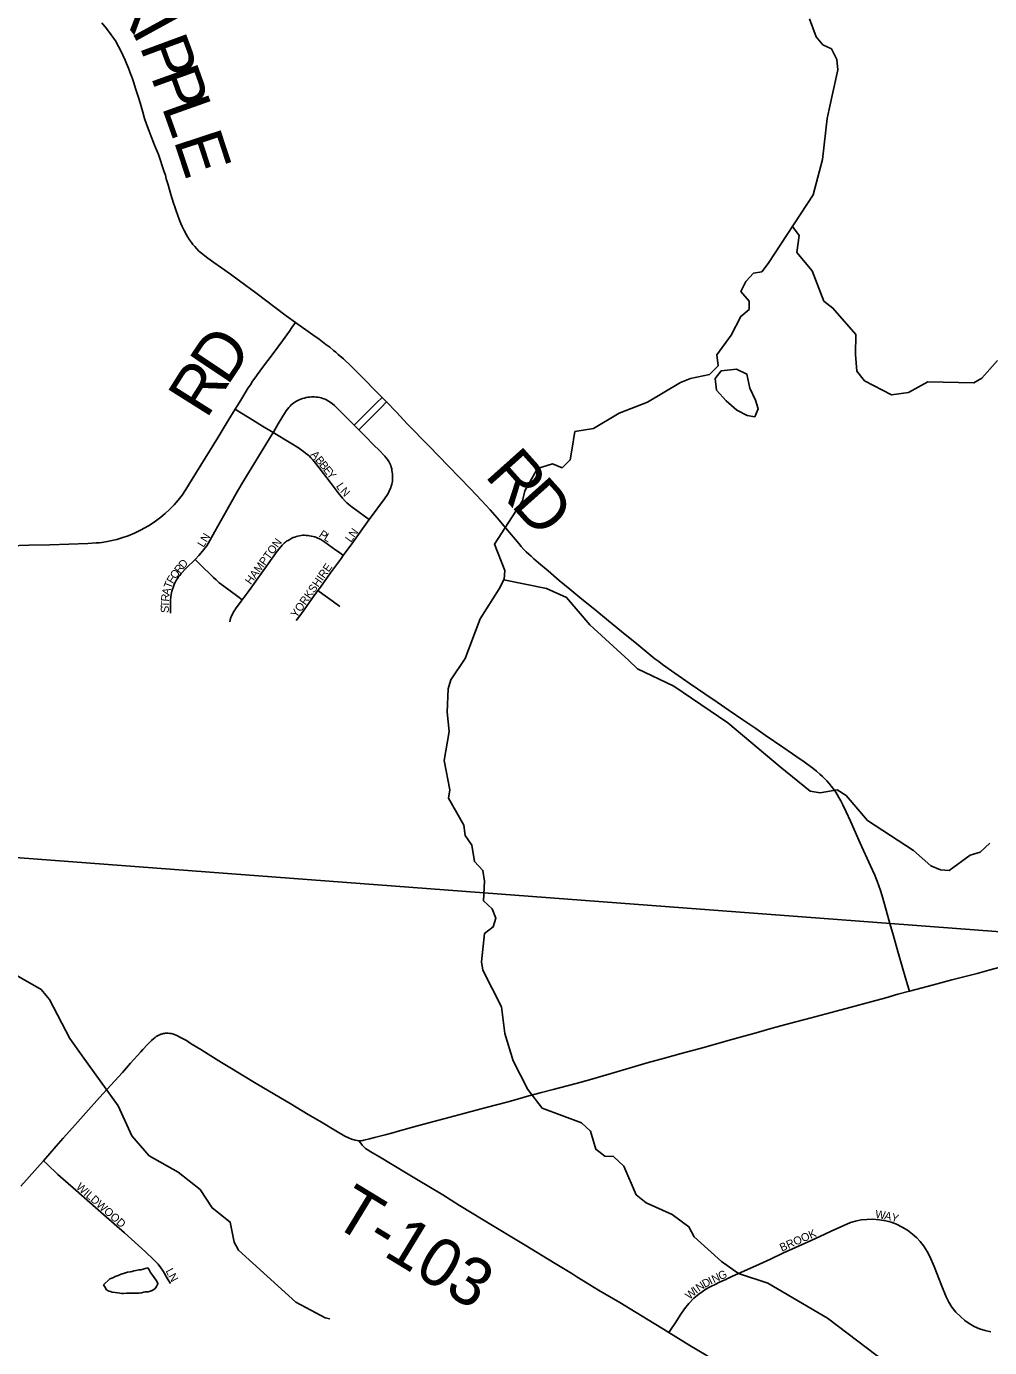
# Model space of a CAD drawing. Extents: x 1410790 to 1770854, y 448063 to 770588.
# Drawn here: x 1538714 to 1544730, y 611215 to 619468 of the extents above; entities that cross this region are included whole.
import ezdxf

# ---------------------------------------------------------------- set-up
doc = ezdxf.new("R2010")
doc.units = 0
for name, color, linetype in [('GM_X_County_Road', 7, 'Continuous'), ('GM_X_County_Road_Text', 7, 'Continuous'), ('GM_X_Minor_Lake', 7, 'Continuous'), ('GM_X_Minor_River', 7, 'Continuous'), ('GM_X_Township', 7, 'Continuous'), ('GM_X_Township_Road', 7, 'Continuous'), ('GM_X_Township_Road_Text', 7, 'Continuous'), ('GM_X_Township_Subdivision', 7, 'Continuous'), ('GM_X_Township_Subdivision_Text', 7, 'Continuous')]:
    doc.layers.add(name, color=color, linetype=linetype)

msp = doc.modelspace()

# ---------------------------------------------------------------- linework, layer by layer
at = {"layer": 'GM_X_County_Road'}
for points in [[(1539185.9, 619491.1), (1539215.3, 619455.5), (1539244.5, 619415.7), (1539270, 619377.2), (1539290.1, 619343.2), (1539302.3, 619319.8), (1539317.4, 619288.8), (1539331.3, 619257.9), (1539340.4, 619235.8), (1539351.7, 619207.6), (1539363, 619177.6), (1539373.8, 619146.8), (1539384.7, 619114.7), (1539395.5, 619080.4), (1539405.9, 619048.3), (1539418.1, 619011), (1539428.9, 618975.4), (1539441.1, 618932.4), (1539452.7, 618893.2), (1539464.5, 618857.3), (1539480.6, 618812.6), (1539492.7, 618780.5), (1539507.5, 618742.8), (1539514.9, 618725.2)], [(1539514.9, 618725.2), (1539527, 618696.3), (1539538.3, 618668.1), (1539550, 618635.5), (1539564.8, 618591.7), (1539575.6, 618558.7), (1539582.1, 618537.9), (1539588.2, 618515.8), (1539599.1, 618478.4), (1539616.9, 618417.2), (1539633.3, 618364.3), (1539640.7, 618341.7), (1539649.8, 618314.8), (1539659.4, 618287.4), (1539670.7, 618256.6), (1539678.1, 618237.5), (1539686.3, 618218.9), (1539698.9, 618193.3), (1539713.2, 618166.3), (1539722.8, 618150.7), (1539733.2, 618135.5), (1539744.7, 618118.1), (1539753.6, 618106.5), (1539765.3, 618092.6), (1539777.4, 618079.6), (1539792.2, 618064.8), (1539807, 618052.2), (1539828.2, 618034.9), (1539847.8, 618020.5), (1539884.6, 617993.6), (1539933.3, 617959.3), (1539988.4, 617920.3), (1540044.3, 617879.3), (1540146.6, 617802.8), (1540337.3, 617659), (1540394.2, 617618.5)], [(1540394.2, 617618.5), (1540502.7, 617541.4), (1540542.2, 617513.2), (1540585.2, 617481.5), (1540609, 617463.2), (1540632, 617444.2), (1540647.2, 617432), (1540662.5, 617419.1), (1540694.3, 617390.5), (1540739.8, 617347.6), (1540823.7, 617264.4), (1540895.5, 617192.3), (1540935.8, 617150.5)], [(1540935.8, 617150.5), (1540963.5, 617121.9)], [(1540963.5, 617121.9), (1541023, 617059.9), (1541095.4, 616984.1), (1541227.6, 616847.4), (1541351.3, 616720.9), (1541488.3, 616579.9), (1541557.9, 616505.7), (1541610.9, 616447.5), (1541654.4, 616398.2), (1541709.3, 616332.8), (1541789.1, 616237.2), (1541805.2, 616218.9), (1541822, 616200.9), (1541836, 616186.3), (1541852, 616171), (1541866.4, 616157.7), (1541883.7, 616142.7), (1541912.4, 616117.8), (1541973.3, 616066.1), (1542042.6, 616007.5), (1542107.7, 615953.3), (1542184.1, 615890.8), (1542265.7, 615825.2), (1542350.4, 615754.5), (1542454.1, 615669), (1542514, 615621.2), (1542565.2, 615578.7), (1542640.3, 615517.5), (1542663.7, 615499.7), (1542688, 615481.9), (1542743.6, 615442.4), (1542853, 615365.9), (1542951.5, 615298.3), (1543027.9, 615245.8), (1543103.4, 615195), (1543189.8, 615136.4), (1543269.6, 615081.9), (1543329.1, 615040.7), (1543440, 614964.5), (1543499.5, 614923.8), (1543540.4, 614894.7), (1543563, 614879.1), (1543588.2, 614861.2), (1543626.4, 614833.5), (1543649, 614814.8), (1543669.4, 614797.5), (1543686.7, 614781.4), (1543701.9, 614766.6), (1543713.2, 614755.3), (1543729.3, 614738.4), (1543741.9, 614722.4), (1543752.7, 614708), (1543769.2, 614684.6), (1543778.3, 614670.3), (1543788.7, 614651.6), (1543800.9, 614629.9), (1543813.4, 614606.1), (1543834.4, 614562), (1543861.2, 614502.7), (1543885.3, 614450), (1543922.8, 614366.5), (1543987.5, 614223.7), (1544013.8, 614165.6), (1544020.9, 614148.1), (1544028.2, 614128.9), (1544048.8, 614069.9), (1544063.5, 614022.8), (1544091.6, 613925), (1544112.6, 613849.1), (1544125.9, 613801.5)], [(1544125.9, 613801.5), (1544158.1, 613688.2), (1544188.3, 613580.9), (1544217.5, 613481.5), (1544229.4, 613441.1)], [(1544229.4, 613441.1), (1544269, 613452), (1544380, 613481.1), (1544494.3, 613510.9), (1544653, 613552.3), (1544725.9, 613571.9), (1544836.7, 613601.9), (1544960.2, 613635.3), (1545037.6, 613655.9)], [(1540791.6, 612506.6), (1540798.9, 612506.4), (1540804.2, 612506.7), (1540814.8, 612508.1), (1540822.1, 612509.5), (1540856.4, 612518.4), (1540888.3, 612526.5), (1540954.5, 612544.5), (1541002.1, 612557.1), (1541030.5, 612564.8), (1541157.2, 612599.4), (1541321.8, 612644), (1541445.6, 612676.2), (1541493, 612689), (1541594.4, 612715.5), (1541714.5, 612748.1), (1541780.7, 612766.8), (1541853.3, 612787), (1541932.5, 612808.2), (1542005.4, 612827.4), (1542091, 612849.8), (1542148, 612864.8), (1542231.8, 612887.9), (1542366.8, 612926.8), (1542458.1, 612953.5), (1542590.7, 612992.8), (1542699.5, 613022.9), (1542804, 613051), (1542946.4, 613090), (1543098.2, 613132.2), (1543180.4, 613154.9), (1543271.9, 613180.7), (1543373.1, 613208.9), (1543480.5, 613238.6), (1543617, 613274.1), (1543772.1, 613316.6), (1544082.5, 613400.3), (1544158.3, 613421.5), (1544229.4, 613441.1)], [(1538820.1, 612382), (1538900.3, 612473.4), (1538943.5, 612522.5), (1539002.7, 612588.2), (1539086.2, 612680.6), (1539171.6, 612775.8), (1539266.3, 612880.4), (1539314.6, 612934), (1539364.6, 612990.5), (1539428.1, 613061.4), (1539441.3, 613076.2), (1539469.8, 613107.6), (1539480.4, 613118.6), (1539495.4, 613132.9), (1539511.3, 613147), (1539518, 613152.3), (1539525.1, 613157.2), (1539540.4, 613166), (1539546.9, 613169.2), (1539550.6, 613170.7), (1539554.1, 613172), (1539558.3, 613173.3), (1539564.4, 613175), (1539569.3, 613176.3), (1539576.4, 613177.6), (1539582.2, 613178.5), (1539586.8, 613178.9), (1539594.3, 613179.2), (1539599.8, 613178.9), (1539610.7, 613177.6), (1539618.8, 613176), (1539632.5, 613172.5), (1539639.4, 613170.2), (1539653.5, 613164.6), (1539681.4, 613150.5), (1539713.8, 613131.9), (1539744.3, 613112.8), (1539802.7, 613076.7), (1539850.1, 613047.3), (1539933.8, 612995.8), (1539995, 612957.7), (1540070.6, 612911.7), (1540149.8, 612865.1), (1540265.2, 612796.1), (1540360.9, 612738.7), (1540473.4, 612671.1), (1540547.5, 612628.9), (1540656.8, 612562.6), (1540702.4, 612536), (1540726.2, 612524), (1540744.2, 612516.6), (1540753, 612513.6), (1540767.4, 612509.5), (1540780.9, 612507.3), (1540788.6, 612506.7), (1540791.6, 612506.6)], [(1538679.1, 612222.4), (1538818.1, 612379.7), (1538820.1, 612382)]]:
    msp.add_lwpolyline(points, dxfattribs=at)
at = {"layer": 'GM_X_Minor_Lake'}
for points in [[(1543264.1, 617028.2), (1543285, 617077.9), (1543268.1, 617132.5), (1543233.4, 617207.5), (1543215.1, 617296.3), (1543149.6, 617325.8), (1543053.2, 617315.9), (1543016.3, 617268.5), (1543024.9, 617196)], [(1543024.9, 617196), (1543085, 617127.9), (1543151.7, 617070.9), (1543216.8, 617037.2), (1543264.1, 617028.2)], [(1539195.4, 611606.3), (1539236.3, 611643.4), (1539254.5, 611651), (1539268.7, 611658.7), (1539286.9, 611664.3), (1539307.1, 611673.8), (1539327.3, 611679.4), (1539345.4, 611684.9), (1539363.5, 611688.5), (1539375.6, 611690.2), (1539385.7, 611694), (1539397.8, 611695.7), (1539415.9, 611699.3), (1539429.9, 611701), (1539444.1, 611704.7), (1539456.2, 611708.4), (1539472.3, 611712), (1539482, 611699.7), (1539489.7, 611683.5), (1539501.3, 611667.2), (1539513, 611652.8), (1539522.7, 611638.5), (1539530.4, 611624.3), (1539536.1, 611612.2), (1539527.8, 611596.3), (1539517.5, 611584.5), (1539503.2, 611572.8), (1539489, 611567.2), (1539474.9, 611563.5), (1539456.9, 611561.9), (1539446.8, 611560.1), (1539432.7, 611556.5), (1539418.6, 611554.8), (1539404.6, 611555.1), (1539380.5, 611553.7), (1539368.5, 611554), (1539354.5, 611554.3), (1539338.5, 611554.7), (1539320.4, 611553.2), (1539310.4, 611553.4), (1539298.4, 611553.7), (1539284.4, 611556), (1539268.5, 611558.4), (1539250.5, 611560.8), (1539238.5, 611565.2), (1539228.6, 611567.4), (1539214.7, 611575.8), (1539203.1, 611594.1), (1539195.4, 611606.3)]]:
    msp.add_lwpolyline(points, dxfattribs=at)
at = {"layer": 'GM_X_Minor_River'}
for points in [[(1543606.1, 619514.3), (1543648, 619403), (1543689.1, 619351.9), (1543742.7, 619328.7), (1543775.5, 619261.7), (1543782.3, 619197.3), (1543729.5, 618951.5), (1543716.3, 618891.6), (1543687.4, 618637.2), (1543629.1, 618415.6), (1543348.5, 617986), (1543307.4, 617934.7), (1543255.2, 617925.8), (1543208.1, 617874.7), (1543176.9, 617811.1), (1543227.8, 617751.8), (1543228.8, 617699.5), (1543175.9, 617656.5), (1543115.6, 617539.4), (1543027.1, 617416.8), (1543035.8, 617348.4), (1542980.7, 617293.4), (1542862.1, 617267.8), (1542799.5, 617243.1), (1542592.9, 617121.1), (1542417.3, 617052.7), (1542257.2, 616955.8), (1542140.7, 616936.3), (1542120.4, 616820.3), (1542111.3, 616760.2), (1542060.3, 616711.2), (1542000.6, 616734.6), (1541905.9, 616706.5), (1541827.1, 616565.7), (1541813.9, 616503.8), (1541638.5, 616232.6), (1541703.5, 616068.5), (1541698.4, 616014.4), (1541667.2, 615954.9), (1541549.5, 615766.8), (1541454.6, 615520), (1541365.9, 615385.4), (1541348.8, 615329.6), (1541342, 615183.2), (1541355.7, 615062.5), (1541324.3, 614882.6), (1541358.8, 614699.2), (1541349.8, 614647.2), (1541446.7, 614478.5), (1541455.5, 614414.1), (1541496.4, 614353), (1541512.4, 614250.3), (1541565.5, 614194.9), (1541576.2, 614128.5), (1541569.9, 614006.2), (1541623, 613954.9), (1541645.9, 613896.2), (1541628.8, 613842.4), (1541576, 613801.4), (1541556.6, 613625.2), (1541565.6, 613572.9), (1541681.4, 613343.6), (1541702.2, 613176.6), (1541755, 613004.9), (1541845.8, 612826.4), (1541935.7, 612710.1), (1542182.3, 612618.4), (1542237.4, 612567), (1542271.3, 612454), (1542326.5, 612410.6), (1542380.5, 612407.4), (1542445.5, 612347.8), (1542522.2, 612169.6), (1542585.3, 612118.1), (1542748.2, 612046.3), (1542852.9, 611969.8), (1542885.7, 611906.9), (1543055, 611752.8)], [(1543499.3, 618217), (1543540.1, 618162.6), (1543526, 618054.5), (1543622, 617941.9), (1543694.5, 617751.6), (1543751.8, 617708.2), (1543894.8, 617542.5), (1543892.4, 617418), (1543900.4, 617313.5), (1543949.4, 617254.2), (1544117.9, 617166.2), (1544224.4, 617181.9), (1544345.8, 617247.5), (1544632.1, 617241.3), (1544682.7, 617270.3), (1544781, 617380.6)], [(1541696.3, 616010.4), (1541963.7, 615956.5), (1542088.8, 615899.5), (1542233.7, 615729.8), (1542477.9, 615507.7), (1542530.9, 615454.3), (1542757.2, 615347), (1543095.3, 615116.8), (1543422.5, 614842.7), (1543609.9, 614690.1), (1543671.8, 614680.7), (1543778.3, 614698.5), (1543835.7, 614663.1), (1543966.9, 614507.7), (1544255.7, 614318.8), (1544308.9, 614271.5), (1544364.1, 614224.1), (1544423.7, 614198.8), (1544477.7, 614195.6), (1544609.7, 614291), (1544672.1, 614309.7), (1544731.3, 614364.6)], [(1538488.3, 613632.2), (1538807.3, 613450.6), (1538858.2, 613389.3), (1538985.7, 613145.8), (1539061.8, 613037.8), (1539288.1, 612723.8), (1539372.7, 612537.4), (1539480.5, 612412.7), (1539662.8, 612310.4), (1539798.9, 612203.1), (1539874.8, 612087), (1539987.3, 611998.3), (1540010.9, 611873.4), (1540038, 611822.7), (1540396.3, 611497.9), (1540521.2, 611431), (1540580.7, 611399.6), (1540608.7, 611395)], [(1543055, 611752.8), (1543161.7, 611678.2), (1543344.8, 611616.1), (1543717.2, 611397.3), (1544029.2, 611163.8), (1544221.3, 611051.3), (1544472, 610963.6), (1544667.5, 610817), (1544718.3, 610751.7), (1545088.1, 610294.3), (1545212.5, 610201.4), (1545320, 610166.9), (1545434.1, 610160.4), (1545437.9, 610152.3)]]:
    msp.add_lwpolyline(points, dxfattribs=at)
at = {"layer": 'GM_X_Township'}
for points in [[(1545541.7, 613754.8), (1544111, 613862.9), (1536959.1, 614403.3), (1531259.4, 614833.9)], [(1531259.4, 614833.9), (1536959.1, 614403.3), (1544111, 613862.9), (1545541.7, 613754.8)]]:
    msp.add_lwpolyline(points, dxfattribs=at)
at = {"layer": 'GM_X_Township_Road'}
for points in [[(1540189.7, 617336.4), (1540255.7, 617424.4), (1540314.3, 617504.2), (1540356.9, 617565), (1540372.9, 617588), (1540394.2, 617618.5)], [(1540018, 617075.9), (1540053.3, 617134), (1540099.8, 617209.4), (1540113, 617229.5), (1540126.8, 617250.8), (1540147.7, 617279.4), (1540155.9, 617290.6)], [(1540155.9, 617290.6), (1540189.7, 617336.4)], [(1538610.4, 616223.7), (1538728.5, 616227.1), (1538859.6, 616230.3), (1539098.9, 616237.7), (1539149, 616240.8), (1539168.1, 616242.5), (1539186.3, 616244.7), (1539220.1, 616249.9), (1539247.9, 616255.5), (1539279.3, 616263.4), (1539310.6, 616272.2), (1539350.5, 616286.2), (1539389.7, 616302.4), (1539427.8, 616320.7), (1539476, 616348.2), (1539511.5, 616371.3), (1539553.7, 616401.9), (1539581.4, 616424.7), (1539609.8, 616451.4), (1539636.9, 616479.6), (1539662.4, 616509.2), (1539686.5, 616540), (1539710.6, 616574.8), (1539750.6, 616638.6), (1539911.3, 616901.8), (1539974.9, 617005.1), (1540018, 617075.9)], [(1540791.6, 612506.6), (1540802.7, 612490.6), (1540810.8, 612478.9), (1540821.2, 612467.8), (1540832.3, 612458.7), (1540841.7, 612452.4), (1540866.2, 612437.2), (1540890.3, 612423.4), (1540918.7, 612406.4), (1541088.4, 612304.1), (1541151.5, 612265.6), (1541314.3, 612168.5), (1541419, 612102.2), (1541636.1, 611970.4), (1541767.3, 611892.1), (1541829.5, 611854.2), (1541867.8, 611830.8), (1541969.8, 611768.5), (1542027.5, 611733.9), (1542121, 611678.1), (1542152.5, 611656.5), (1542288.5, 611573.1), (1542420.2, 611495.8), (1542522.8, 611434.2), (1542634.9, 611365.1), (1542693.6, 611329.2), (1542727.3, 611308.7)], [(1542727.3, 611308.7), (1542858.8, 611228.4), (1542959.3, 611166.6), (1542987, 611149.3)]]:
    msp.add_lwpolyline(points, dxfattribs=at)
at = {"layer": 'GM_X_Township_Subdivision'}
for points in [[(1540255.7, 616930.7), (1540257.5, 616933.6), (1540287.5, 616984.4), (1540315.3, 617032.8), (1540336.9, 617065.7), (1540344.1, 617075.8), (1540352.9, 617086.5), (1540361.2, 617095.3), (1540368.8, 617103), (1540376, 617109.2), (1540384, 617115.5), (1540391.6, 617120.9), (1540400.5, 617126.2), (1540408.8, 617130.7), (1540418, 617135.2), (1540427.4, 617138.9), (1540439.5, 617143.3), (1540450.9, 617146.5), (1540461.7, 617149.2), (1540472.1, 617151.1), (1540483.9, 617152.6), (1540494.3, 617153.5), (1540504, 617153.9), (1540513.2, 617153.7), (1540523.6, 617152.8), (1540535.1, 617151.3), (1540546.3, 617149.2), (1540555.9, 617146.9), (1540565.3, 617144.1), (1540574.3, 617140.6), (1540583.5, 617136.7), (1540600.8, 617127.3), (1540610.6, 617121.3), (1540625.5, 617111.1), (1540638, 617100.5), (1540667.9, 617070.1), (1540740.2, 616997.7), (1540760.8, 616977.6)], [(1540760.8, 616977.6), (1540771, 616987.3), (1540784.1, 616999.9), (1540901.5, 617116.4), (1540935.8, 617150.5)], [(1540790.3, 616948.4), (1540815.4, 616973.1), (1540848.8, 617006.1), (1540907.8, 617065.2), (1540929.5, 617087.3), (1540963.5, 617121.9)], [(1540018, 617075.9), (1540046.3, 617058.5), (1540105.1, 617022.6), (1540189, 616971.1), (1540255.7, 616930.7)], [(1540760.8, 616977.6), (1540775.7, 616962.8)], [(1540790.3, 616948.4), (1540775.7, 616962.8)], [(1540856.1, 616387.1), (1540951.4, 616517.2), (1540969.7, 616544.4), (1540975.7, 616555), (1540980.7, 616564.5), (1540985.3, 616574.5), (1540989.6, 616585.7), (1540993.1, 616596.2), (1540996.4, 616607.6), (1540998.5, 616617.5), (1541000.1, 616626.9), (1541001.1, 616636.3), (1541001.7, 616646.5), (1541001.5, 616658.1), (1541000.9, 616672.7), (1540999.8, 616683.4), (1540997.8, 616694.5), (1540995.9, 616704.9), (1540993.3, 616714.5), (1540989.8, 616724), (1540986.1, 616732.8), (1540981.9, 616741.7), (1540977.1, 616750.8), (1540970.2, 616761.7), (1540960.2, 616775.1), (1540953.2, 616783.7), (1540945.7, 616792.2), (1540922.7, 616815.6), (1540880.3, 616857.1), (1540835.6, 616901.9), (1540790.3, 616948.4)], [(1539767.4, 616137.6), (1539791.3, 616162.4), (1539814.8, 616189.6), (1539822.8, 616199.5), (1539830.8, 616210.4), (1539840.2, 616223.8), (1539848.9, 616237.8), (1539891.3, 616311.8), (1539965.9, 616446.8), (1540032.2, 616563.8), (1540072.4, 616631.4), (1540187.5, 616818.7), (1540255.7, 616930.7)], [(1540255.7, 616930.7), (1540365.8, 616864), (1540413.2, 616834.6), (1540429.9, 616823.4), (1540445.6, 616812.1), (1540458.1, 616802.5), (1540471.2, 616791.6), (1540481.6, 616782.6), (1540490.3, 616773.6), (1540500.2, 616763), (1540512.2, 616749.3), (1540542.7, 616710.7), (1540617.4, 616612), (1540660.8, 616554.7), (1540689, 616520), (1540705.5, 616502.2), (1540715.9, 616492.2), (1540728.9, 616480.9), (1540749.8, 616464.4), (1540777.4, 616443.1), (1540825.5, 616408.8), (1540856.1, 616387.1)], [(1540693.6, 616163), (1540747.3, 616236), (1540856.1, 616387.1)], [(1540062.3, 615885.8), (1540105.3, 615944.2), (1540281.3, 616188.8), (1540303.4, 616217.8), (1540310.9, 616226.4), (1540319.3, 616235.1), (1540325.4, 616240.8), (1540332.1, 616246.1), (1540339.7, 616251.6), (1540348.2, 616257.2), (1540358.8, 616263.5), (1540372.3, 616270.2), (1540381.4, 616274.2), (1540390.9, 616277.9), (1540400.9, 616281.5), (1540410.2, 616284.1), (1540420.2, 616286.1), (1540430.2, 616287.6), (1540441.3, 616288.7), (1540450.8, 616288.9), (1540461.3, 616288.5), (1540473.8, 616287.5), (1540483.4, 616286.1), (1540493.7, 616284.4), (1540504.6, 616281.8), (1540516.4, 616278.4), (1540525.7, 616275), (1540535.2, 616270.9), (1540544.6, 616266.6), (1540553.2, 616262.1), (1540565.8, 616254.4), (1540578.5, 616246.1), (1540647.9, 616196.1), (1540669.1, 616180.8), (1540693.6, 616163)], [(1539614.9, 615801.9), (1539614.3, 615823.6), (1539613.8, 615844.4), (1539613.7, 615859.7), (1539614, 615873.9), (1539614.9, 615885.9), (1539616.2, 615902.1), (1539618.4, 615918.4), (1539620.6, 615930.1), (1539623.2, 615940.8), (1539626.4, 615951.9), (1539630.1, 615962.7), (1539635.1, 615976.2), (1539640, 615987), (1539646, 615998.7), (1539652.1, 616010.3), (1539657.9, 616019.6), (1539664.7, 616029.5), (1539671.8, 616038.7), (1539681.2, 616049.9), (1539712.4, 616083.6), (1539767.4, 616137.6)], [(1539767.4, 616137.6), (1539795.8, 616110.1), (1539882.7, 616025.7), (1539899.6, 616009.8), (1539919, 615992.8), (1539933.5, 615980.7), (1539946.9, 615970.4), (1540034, 615906.6), (1540062.3, 615885.8)], [(1540534.5, 615943.5), (1540550.5, 615965.8), (1540613.9, 616053.4), (1540675.5, 616138.3), (1540693.6, 616163)], [(1540400, 615757.2), (1540415.1, 615776.6), (1540449.9, 615824.2), (1540496.9, 615891.3), (1540534.5, 615943.5)], [(1540534.5, 615943.5), (1540565.3, 615921.3), (1540623.7, 615879.2), (1540672.9, 615843.7)], [(1539984.9, 615748.3), (1539989.9, 615769.6), (1539991.4, 615775.2), (1539993.1, 615780.3), (1539995.5, 615785.9), (1540000.8, 615795.9), (1540005.1, 615804.3), (1540008.8, 615810.8), (1540015.3, 615821.3), (1540020.9, 615829.5), (1540056.7, 615878.3), (1540062.3, 615885.8)], [(1538820.1, 612382), (1538843.6, 612359.7), (1538910.1, 612296.8), (1539023.6, 612197.8), (1539109.7, 612121.6), (1539198.1, 612043.3), (1539326.3, 611930.7), (1539458.8, 611813), (1539509, 611765.5), (1539536.2, 611736.5), (1539554.5, 611712.9), (1539569.3, 611690.9), (1539595, 611644.7), (1539613.3, 611615.6)], [(1542727.3, 611308.7), (1542739.3, 611326.6), (1542770, 611372.7), (1542797.4, 611417.2), (1542825.3, 611457.4), (1542852.3, 611489.8), (1542884.2, 611522.4), (1542913.5, 611548), (1542935.6, 611563.8), (1542958.7, 611578.6), (1542981.6, 611592), (1543025.4, 611613.5), (1543039.6, 611620.3), (1543048, 611624.3), (1543053.8, 611627.1), (1543062.4, 611631.2), (1543068.3, 611634), (1543082.8, 611640.8), (1543088.9, 611643.6), (1543100.7, 611649), (1543124.4, 611659.9), (1543270.9, 611725.9), (1543361.4, 611767.8), (1543440, 611803.8), (1543597, 611875.7), (1543665, 611906), (1543742, 611942.7), (1543819.6, 611977.7), (1543861.7, 611995), (1543892.6, 612004.6), (1543927.5, 612011.6), (1543962.8, 612015.6), (1543998.5, 612016.4), (1544043.9, 612013.2), (1544082.2, 612007.1), (1544116.6, 611997.9), (1544149.7, 611984.8), (1544184.5, 611967.3), (1544217.8, 611947.1), (1544249, 611923.9), (1544275.5, 611900), (1544297.3, 611876.2), (1544318.9, 611847.8), (1544339.8, 611814.9), (1544356.5, 611783.4), (1544383.4, 611720.2), (1544432.5, 611598.5), (1544459.2, 611531.2), (1544475.9, 611498.6), (1544495.6, 611467.9), (1544520.4, 611436.6), (1544548.1, 611407.9), (1544575.9, 611384.1), (1544603.2, 611365.1), (1544635, 611347.1), (1544668.5, 611332.2), (1544703.2, 611320.6), (1544739, 611312.9)]]:
    msp.add_lwpolyline(points, dxfattribs=at)

# ---------------------------------------------------------------- texts
at = {"layer": 'GM_X_County_Road_Text'}
for s, rotation, p in [('R', 308.58118, (1539219, 619624.4)), ('I', 298.72291, (1539365.1, 619443.2)), ('P', 290.24963, (1539419.5, 619345.8)), ('P', 289.75579, (1539489.3, 619156.5)), ('L', 289.63106, (1539557.6, 618966.2)), ('E', 288.21744, (1539632.4, 618756.7)), ('R', 311.79691, (1541571.2, 616660)), ('D', 311.88948, (1541735.8, 616475.9))]:
    msp.add_text(s, height=300, rotation=rotation, dxfattribs=at).set_placement(p)
at = {"layer": 'GM_X_Township_Road_Text'}
for s, rotation, p in [('D', 56.17252, (1539968.8, 617217.3)), ('R', 57.80555, (1539838.7, 617010.7)), ('T-103', 328.66231, (1540612.9, 611989.4))]:
    msp.add_text(s, height=300, rotation=rotation, dxfattribs=at).set_placement(p)
at = {"layer": 'GM_X_Township_Subdivision_Text'}
for s, rotation, p in [('A', 310.78501, (1540486.7, 616791.3)), ('B', 309.05617, (1540515.2, 616758.3)), ('B', 308.44365, (1540540.1, 616727.7)), ('E', 308.41658, (1540564.7, 616696.7)), ('Y', 308.41747, (1540586.6, 616669.1)), ('L', 304.45927, (1540646.4, 616596)), ('N', 312.82702, (1540671.2, 616560.9)), ('LN', 58.2398, (1539820.7, 616209.4)), ('P', 326.48422, (1540537, 616283.1)), ('L', 329.01005, (1540568.3, 616262.4)), ('LN', 53.7411, (1540740.7, 616240.7)), ('HAMPTON', 53.79018, (1540115.9, 615976.7)), ('D', 48.10052, (1539696, 616077.1)), ('YORKSHIRE', 54.95135, (1540401.7, 615769.7)), ('F', 58.45515, (1539628.3, 615982.6)), ('O', 53.11698, (1539646, 616011.6)), ('R', 52.16336, (1539672.3, 616046.6)), ('A', 76.36656, (1539607, 615910.7)), ('T', 69.16255, (1539616.9, 615951.9)), ('T', 89.71914, (1539603.8, 615839.1)), ('R', 85.10124, (1539603.9, 615873.3)), ('S', 89.7131, (1539603.6, 615803.9)), ('WILDWOOD', 318.54167, (1539020.9, 612211.9)), ('W', 351.97095, (1544014, 612025)), ('A', 346.49917, (1544069.4, 612017.2)), ('Y', 343.94352, (1544111.6, 612007.1)), ('BROOK', 23.96061, (1543432.8, 611813)), ('L', 296.95611, (1539581.9, 611694.1)), ('N', 298.55382, (1539598.5, 611661.4)), ('I', 26.45753, (1542989.5, 611606.7)), ('N', 26.09101, (1543009.1, 611616.4)), ('G', 23.0436, (1543048, 611635.5)), ('W', 42.37207, (1542857.5, 611511.4)), ('I', 37.73119, (1542899, 611549.3)), ('N', 34.02954, (1542915.7, 611562.3)), ('D', 28.03648, (1542951, 611586.2))]:
    msp.add_text(s, height=50, rotation=rotation, dxfattribs=at).set_placement(p)

doc.saveas('drawing.dxf')
